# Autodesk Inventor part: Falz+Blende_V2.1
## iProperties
Created: 2008-06
Part Number: Falz+Blende_V2.1
Document SubType Name: Blech
Designer: Dirk
Density: 1 g/cm^3
Author: Dirk
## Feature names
1. Runde Anordnung3 [Circular Pattern]
2. Grobblech1
3. Grobblech2
4. Biegung1
5. Grobblech3
6. Biegung2
7. Grobblech4
8. Biegung3
9. Grobblech5
10. Biegung4
11. Grobblech6
12. Biegung5
13. Ecke6
14. Ecke11
15. Ecke12
16. Ecke13
